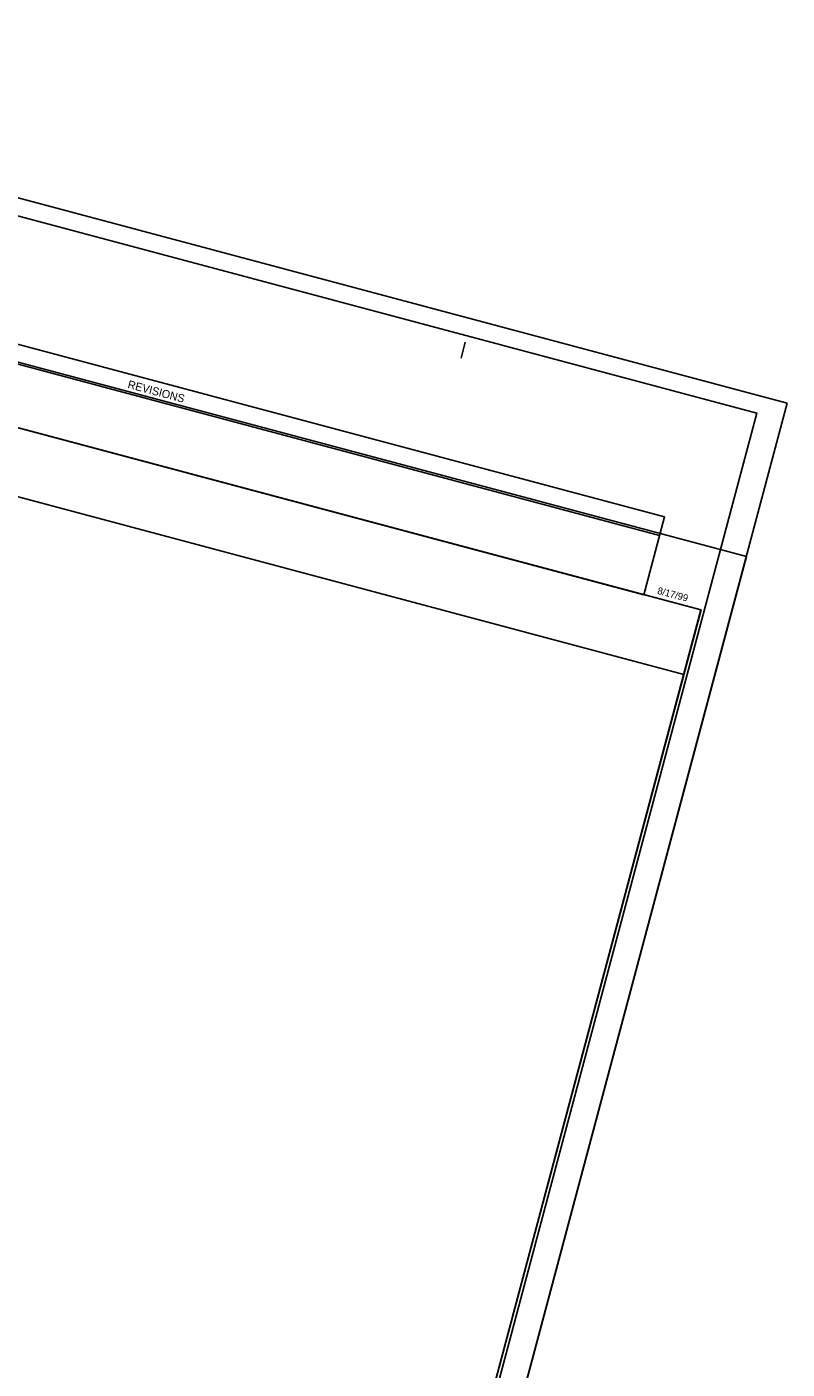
# Model space of a CAD drawing. Extents: x 1778994 to 1784559, y 810461 to 816654.
# Drawn here: x 1783105 to 1783675, y 815048 to 816054 of the extents above; entities that cross this region are included whole.
import ezdxf

# ---------------------------------------------------------------- set-up
doc = ezdxf.new("R2010")
doc.units = 0
for name, color, linetype in [('Sheet Block Revision CELL', 7, 'Continuous'), ('Sheet Clip Boundary CELL', 7, 'Continuous'), ('Sheet Cutting Line CELL', 7, 'Continuous'), ('Sheet Layout Plan Border', 7, 'Continuous'), ('Sheet Plan CELL', 7, 'Continuous'), ('Sheet Plan Layout CELL', 7, 'Continuous'), ('Sheet Plot Border Inside CELL', 7, 'Continuous'), ('Sheet Plot Border Outside CELL', 7, 'Continuous')]:
    doc.layers.add(name, color=color, linetype=linetype)

msp = doc.modelspace()

# ---------------------------------------------------------------- linework, layer by layer
at = {"layer": 'Sheet Block Revision CELL'}
msp.add_line((1782815.8, 815876.7), (1783579.7, 815672.9), dxfattribs=at)
msp.add_lwpolyline([(1782819.5, 815890.7), (1783583.5, 815687), (1783567.9, 815628.5), (1782804, 815832.2)], close=True, dxfattribs=at)
at = {"layer": 'Sheet Clip Boundary CELL'}
msp.add_lwpolyline([(1782583.3, 815839.3), (1782222.6, 814486.6), (1783032.8, 814270.5), (1783081.5, 814453.4), (1783285.9, 814398.9), (1783597.9, 815568.8)], close=True, dxfattribs=at)
at = {"layer": 'Sheet Cutting Line CELL'}
for p, q in [((1783675.4, 815772.2), (1782617.4, 816054.3)), ((1783241.6, 814145.5), (1783675.4, 815772.2))]:
    msp.add_line(p, q, dxfattribs=at)
at = {"layer": 'Sheet Layout Plan Border'}
msp.add_lwpolyline([(1782583.3, 815839.3), (1782222.6, 814486.6), (1783032.8, 814270.5), (1783081.5, 814453.4), (1783285.9, 814398.9), (1783597.9, 815568.8)], close=True, dxfattribs=at)
at = {"layer": 'Sheet Plan CELL'}
for p, q in [((1783434, 815817.9), (1783430.8, 815805.8)), ((1783610.8, 815617.1), (1783610.8, 815617.1))]:
    msp.add_line(p, q, dxfattribs=at)
for points in [[(1783224.2, 814167.7), (1783610.8, 815617.1), (1782596.2, 815887.7), (1782209.7, 814438.3)], [(1782596.2, 815887.7), (1783610.7, 815617.1), (1783275.8, 814361), (1783130.8, 814399.7), (1783079.2, 814206.4), (1782209.7, 814438.3)]]:
    msp.add_lwpolyline(points, close=True, dxfattribs=at)
at = {"layer": 'Sheet Plan Layout CELL'}
msp.add_lwpolyline([(1783610.7, 815617.1), (1782596.2, 815887.7), (1782209.7, 814438.3), (1783019.9, 814222.2), (1783081.5, 814453.4), (1783285.9, 814398.9)], close=True, dxfattribs=at)
at = {"layer": 'Sheet Plot Border Inside CELL'}
msp.add_lwpolyline([(1782633.3, 816036.6), (1782204.1, 814426.9), (1783223.4, 814155), (1783652.7, 815764.7)], close=True, dxfattribs=at)
at = {"layer": 'Sheet Plot Border Outside CELL'}
msp.add_lwpolyline([(1782586.7, 815939.4), (1782152.9, 814312.8), (1783210.9, 814030.6), (1783644.8, 815657.3)], close=True, dxfattribs=at)

# ---------------------------------------------------------------- texts
at = {"layer": 'Sheet Block Revision CELL'}
msp.add_text('REVISIONS', height=6, rotation=345.0673, dxfattribs=at).set_placement((1783180.3, 815783.7))
at = {"layer": 'Sheet Plan CELL'}
msp.add_text('8/17/99', height=5.25, rotation=345.0673, dxfattribs=at).set_placement((1783577.6, 815629.3))

doc.saveas('drawing.dxf')
